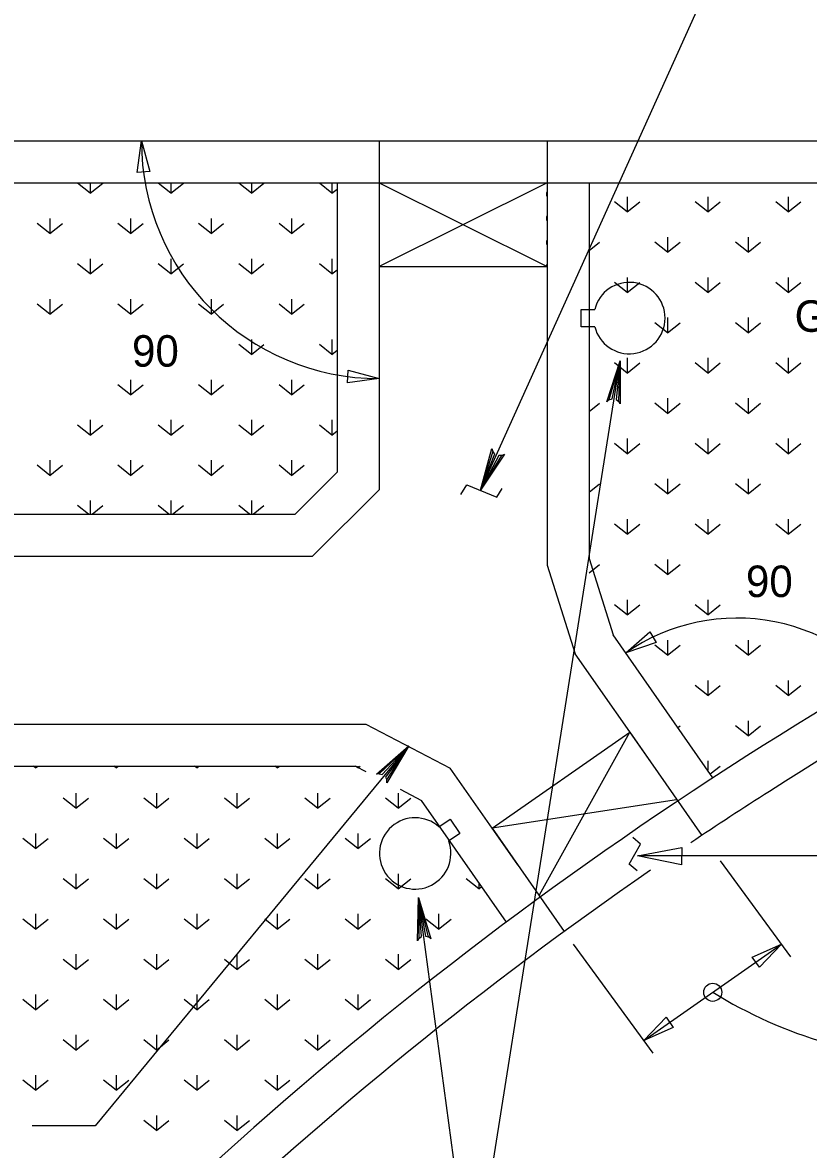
# Model space of a CAD drawing. Extents: x 36 to 940, y -1166 to 1210.
# Drawn here: x 481.8 to 556.7, y -1059.4 to -952.1 of the extents above; entities that cross this region are included whole.
import ezdxf

# ---------------------------------------------------------------- set-up
doc = ezdxf.new("R2010")
doc.units = 0
for name, color, linetype in [('1', 7, 'Continuous'), ('2', 7, 'Continuous'), ('Default', 7, 'Continuous')]:
    doc.layers.add(name, color=color, linetype=linetype)

msp = doc.modelspace()

# ---------------------------------------------------------------- linework, layer by layer
at = {"layer": '1'}
for points in [[(523.61, -997.02), (524.19, -996.11), (527.03, -997.29), (527.56, -996.47)], [(540.43, -1032.88), (539.66, -1032.25), (540.74, -1030.36), (540, -1029.72)]]:
    msp.add_lwpolyline(points, dxfattribs=at)
msp.add_circle((547.62, -1044.46), 0.864, dxfattribs=at)
at = {"layer": '2'}
for p, q in [((515.76, -967.31), (531.84, -975.32)), ((531.72, -967.41), (515.84, -975.32)), ((535.07, -981.05), (535.07, -979.4)), ((535.07, -979.4), (536.37, -979.4)), ((536.37, -981.05), (535.07, -981.05)), ((524.67, -1073.35), (538.81, -984.29)), ((531.11, -1035.18), (539.71, -1019.67)), ((544.15, -1026.13), (526.59, -1028.83)), ((521.52, -1028.69), (522.6, -1027.96)), ((522.6, -1027.96), (523.53, -1029.33)), ((523.53, -1029.33), (522.45, -1030.06)), ((524.67, -1073.35), (519.57, -1035.44))]:
    msp.add_line(p, q, dxfattribs=at)
for points in [[(537.72, -988.02), (538.02, -987.93), (538.81, -984.29), (537.72, -988.02), (537.53, -988.19), (538.81, -984.29), (538.41, -987.98), (538.66, -988.16), (538.81, -984.29), (538.81, -988.4), (538.66, -988.16)], [(527.53, -993.31), (527.22, -993.32), (525.5, -996.63), (527.53, -993.31), (527.77, -993.2), (525.5, -996.63), (526.86, -993.17), (526.66, -992.93), (525.5, -996.63), (526.58, -992.66), (526.66, -992.93)], [(515.83, -1023.64), (516.13, -1023.7), (518.66, -1020.97), (515.83, -1023.64), (515.57, -1023.68), (518.66, -1020.97), (516.43, -1023.95), (516.56, -1024.23), (518.66, -1020.97), (516.57, -1024.51), (516.56, -1024.23)], [(519.61, -1039.33), (519.87, -1039.15), (519.57, -1035.44), (519.61, -1039.33), (519.47, -1039.55), (519.57, -1035.44), (520.25, -1039.1), (520.54, -1039.19), (519.57, -1035.44), (520.75, -1039.38), (520.54, -1039.19)]]:
    msp.add_lwpolyline(points, dxfattribs=at)
for centre, start, end in [((539.67, -980.22), 194.1014, 165.8986), ((519.26, -1031.23), 48.2263, 20.0236)]:
    msp.add_arc(centre, 3.4, start, end, dxfattribs=at)
at = {"layer": 'Default'}
for p, q in [((525.5, -996.63), (548.63, -945.31)), ((452.2, -963.32), (656.79, -963.32)), ((515.84, -963.32), (515.84, -996.57)), ((531.84, -963.32), (531.84, -975.32)), ((452.2, -967.32), (656.79, -967.32)), ((488.29, -968.33), (487.09, -967.37)), ((488.29, -967.32), (488.29, -968.33)), ((488.29, -968.33), (489.49, -967.37)), ((495.97, -968.33), (494.77, -967.37)), ((495.97, -967.32), (495.97, -968.33)), ((495.97, -968.33), (497.17, -967.37)), ((503.65, -968.33), (502.45, -967.37)), ((503.65, -967.32), (503.65, -968.33)), ((503.65, -968.33), (504.85, -967.37)), ((511.33, -968.33), (510.13, -967.37)), ((511.33, -967.32), (511.33, -968.33)), ((511.84, -967.32), (511.84, -994.91)), ((515.84, -967.32), (515.84, -975.32)), ((535.84, -967.32), (535.84, -1003.13)), ((511.33, -968.33), (511.84, -967.93)), ((539.46, -970.1), (538.26, -969.14)), ((539.46, -968.66), (539.46, -970.1)), ((539.46, -970.1), (540.66, -969.14)), ((547.14, -970.1), (545.94, -969.14)), ((547.14, -968.66), (547.14, -970.1)), ((547.14, -970.1), (548.34, -969.14)), ((554.82, -970.1), (553.62, -969.14)), ((554.82, -968.66), (554.82, -970.1)), ((554.82, -970.1), (556.02, -969.14)), ((484.45, -972.17), (483.25, -971.21)), ((484.45, -970.73), (484.45, -972.17)), ((484.45, -972.17), (485.65, -971.21)), ((492.13, -972.17), (490.93, -971.21)), ((492.13, -970.73), (492.13, -972.17)), ((492.13, -972.17), (493.33, -971.21)), ((499.81, -972.17), (498.61, -971.21)), ((499.81, -970.73), (499.81, -972.17)), ((499.81, -972.17), (501.01, -971.21)), ((507.49, -972.17), (506.29, -971.21)), ((507.49, -970.73), (507.49, -972.17)), ((507.49, -972.17), (508.69, -971.21)), ((531.84, -971.32), (531.84, -1003.75)), ((543.3, -972.5), (543.3, -973.94)), ((550.98, -972.5), (550.98, -973.94)), ((535.84, -973.77), (536.82, -972.98)), ((543.3, -973.94), (542.1, -972.98)), ((543.3, -973.94), (544.5, -972.98)), ((550.98, -973.94), (549.78, -972.98)), ((550.98, -973.94), (552.18, -972.98)), ((488.29, -974.57), (488.29, -976.01)), ((495.97, -974.57), (495.97, -976.01)), ((503.65, -974.57), (503.65, -976.01)), ((511.33, -974.57), (511.33, -976.01)), ((488.29, -976.01), (487.09, -975.05)), ((488.29, -976.01), (489.49, -975.05)), ((495.97, -976.01), (494.77, -975.05)), ((495.97, -976.01), (497.17, -975.05)), ((503.65, -976.01), (502.45, -975.05)), ((503.65, -976.01), (504.85, -975.05)), ((511.33, -976.01), (510.13, -975.05)), ((511.33, -976.01), (511.84, -975.61)), ((515.84, -975.32), (531.84, -975.32)), ((539.46, -977.78), (538.26, -976.82)), ((539.46, -976.34), (539.46, -977.78)), ((539.46, -977.78), (540.66, -976.82)), ((547.14, -977.78), (545.94, -976.82)), ((547.14, -976.34), (547.14, -977.78)), ((547.14, -977.78), (548.34, -976.82)), ((554.82, -977.78), (553.62, -976.82)), ((554.82, -976.34), (554.82, -977.78)), ((554.82, -977.78), (556.02, -976.82)), ((484.45, -979.85), (483.25, -978.89)), ((484.45, -978.41), (484.45, -979.85)), ((484.45, -979.85), (485.65, -978.89)), ((492.13, -979.85), (490.93, -978.89)), ((492.13, -978.41), (492.13, -979.85)), ((492.13, -979.85), (493.33, -978.89)), ((499.81, -979.85), (498.61, -978.89)), ((499.81, -978.41), (499.81, -979.85)), ((499.81, -979.85), (501.01, -978.89)), ((507.49, -979.85), (506.29, -978.89)), ((507.49, -978.41), (507.49, -979.85)), ((507.49, -979.85), (508.69, -978.89)), ((543.3, -980.18), (543.3, -981.62)), ((550.98, -980.18), (550.98, -981.62)), ((543.3, -981.62), (542.1, -980.66)), ((543.3, -981.62), (544.5, -980.66)), ((550.98, -981.62), (549.78, -980.66)), ((550.98, -981.62), (552.18, -980.66)), ((503.65, -982.25), (503.65, -983.69)), ((511.33, -982.25), (511.33, -983.69)), ((503.65, -983.69), (502.45, -982.73)), ((503.65, -983.69), (504.85, -982.73)), ((511.33, -983.69), (510.13, -982.73)), ((511.33, -983.69), (511.84, -983.29)), ((539.46, -985.46), (538.26, -984.5)), ((539.46, -984.02), (539.46, -985.46)), ((539.46, -985.46), (540.66, -984.5)), ((547.14, -985.46), (545.94, -984.5)), ((547.14, -984.02), (547.14, -985.46)), ((547.14, -985.46), (548.34, -984.5)), ((554.82, -985.46), (553.62, -984.5)), ((554.82, -984.02), (554.82, -985.46)), ((554.82, -985.46), (556.02, -984.5)), ((492.13, -987.53), (490.93, -986.57)), ((492.13, -986.09), (492.13, -987.53)), ((492.13, -987.53), (493.33, -986.57)), ((499.81, -987.53), (498.61, -986.57)), ((499.81, -986.09), (499.81, -987.53)), ((499.81, -987.53), (501.01, -986.57)), ((507.49, -987.53), (506.29, -986.57)), ((507.49, -986.09), (507.49, -987.53)), ((507.49, -987.53), (508.69, -986.57)), ((535.84, -989.13), (536.82, -988.34)), ((543.3, -989.3), (542.1, -988.34)), ((543.3, -987.86), (543.3, -989.3)), ((543.3, -989.3), (544.5, -988.34)), ((550.98, -989.3), (549.78, -988.34)), ((550.98, -987.86), (550.98, -989.3)), ((550.98, -989.3), (552.18, -988.34)), ((488.29, -989.93), (488.29, -991.37)), ((495.97, -989.93), (495.97, -991.37)), ((503.65, -989.93), (503.65, -991.37)), ((511.33, -989.93), (511.33, -991.37)), ((488.29, -991.37), (487.09, -990.41)), ((488.29, -991.37), (489.49, -990.41)), ((495.97, -991.37), (494.77, -990.41)), ((495.97, -991.37), (497.17, -990.41)), ((503.65, -991.37), (502.45, -990.41)), ((503.65, -991.37), (504.85, -990.41)), ((511.33, -991.37), (510.13, -990.41)), ((511.33, -991.37), (511.84, -990.97)), ((539.46, -991.7), (539.46, -993.14)), ((547.14, -991.7), (547.14, -993.14)), ((554.82, -991.7), (554.82, -993.14)), ((539.46, -993.14), (538.26, -992.18)), ((539.46, -993.14), (540.66, -992.18)), ((547.14, -993.14), (545.94, -992.18)), ((547.14, -993.14), (548.34, -992.18)), ((554.82, -993.14), (553.62, -992.18)), ((554.82, -993.14), (556.02, -992.18)), ((484.45, -995.21), (483.25, -994.25)), ((484.45, -993.77), (484.45, -995.21)), ((484.45, -995.21), (485.65, -994.25)), ((492.13, -995.21), (490.93, -994.25)), ((492.13, -993.77), (492.13, -995.21)), ((492.13, -995.21), (493.33, -994.25)), ((499.81, -995.21), (498.61, -994.25)), ((499.81, -993.77), (499.81, -995.21)), ((499.81, -995.21), (501.01, -994.25)), ((507.49, -995.21), (506.29, -994.25)), ((507.49, -993.77), (507.49, -995.21)), ((507.49, -995.21), (508.69, -994.25)), ((507.84, -998.91), (511.84, -994.91)), ((535.84, -996.81), (536.82, -996.02)), ((543.3, -996.98), (542.1, -996.02)), ((543.3, -995.54), (543.3, -996.98)), ((543.3, -996.98), (544.5, -996.02)), ((550.98, -996.98), (549.78, -996.02)), ((550.98, -995.54), (550.98, -996.98)), ((550.98, -996.98), (552.18, -996.02)), ((509.49, -1002.91), (515.84, -996.57)), ((488.12, -998.91), (487.09, -998.09)), ((488.29, -997.61), (488.29, -998.91)), ((488.47, -998.91), (489.49, -998.09)), ((495.8, -998.91), (494.77, -998.09)), ((495.97, -997.61), (495.97, -998.91)), ((496.15, -998.91), (497.17, -998.09)), ((503.48, -998.91), (502.45, -998.09)), ((503.65, -997.61), (503.65, -998.91)), ((503.83, -998.91), (504.85, -998.09)), ((448.2, -998.91), (507.84, -998.91)), ((539.46, -999.38), (539.46, -1000.82)), ((547.14, -999.38), (547.14, -1000.82)), ((554.82, -999.38), (554.82, -1000.82)), ((539.46, -1000.82), (538.26, -999.86)), ((539.46, -1000.82), (540.66, -999.86)), ((547.14, -1000.82), (545.94, -999.86)), ((547.14, -1000.82), (548.34, -999.86)), ((554.82, -1000.82), (553.62, -999.86)), ((554.82, -1000.82), (556.02, -999.86)), ((444.2, -1002.91), (509.49, -1002.91)), ((531.84, -1003.75), (534.5, -1012.2)), ((535.84, -1003.13), (538.13, -1010.41)), ((535.84, -1004.49), (536.82, -1003.7)), ((543.3, -1004.66), (542.1, -1003.7)), ((543.3, -1003.22), (543.3, -1004.66)), ((543.3, -1004.66), (544.5, -1003.7)), ((539.46, -1007.06), (539.46, -1008.5)), ((547.14, -1007.06), (547.14, -1008.5)), ((539.46, -1008.5), (538.26, -1007.54)), ((539.46, -1008.5), (540.66, -1007.54)), ((547.14, -1008.5), (545.94, -1007.54)), ((547.14, -1008.5), (548.34, -1007.54)), ((547.63, -1024.02), (538.13, -1010.41)), ((543.3, -1012.34), (542.1, -1011.38)), ((543.3, -1010.9), (543.3, -1012.34)), ((543.3, -1012.34), (544.5, -1011.38)), ((550.98, -1012.34), (549.78, -1011.38)), ((550.98, -1010.9), (550.98, -1012.34)), ((550.98, -1012.34), (552.18, -1011.38)), ((542.15, -1023.15), (534.5, -1012.2)), ((547.14, -1016.18), (545.94, -1015.22)), ((547.14, -1014.74), (547.14, -1016.18)), ((547.14, -1016.18), (548.34, -1015.22)), ((554.82, -1016.18), (553.62, -1015.22)), ((554.82, -1014.74), (554.82, -1016.18)), ((554.82, -1016.18), (556.02, -1015.22)), ((444.2, -1018.91), (514.56, -1018.91)), ((514.56, -1018.91), (522.59, -1023.1)), ((550.98, -1018.58), (550.98, -1020.02)), ((526.59, -1028.83), (539.71, -1019.67)), ((539.71, -1019.67), (546.59, -1029.51)), ((544.29, -1019.23), (544.5, -1019.06)), ((550.98, -1020.02), (549.78, -1019.06)), ((550.98, -1020.02), (552.18, -1019.06)), ((518.66, -1020.97), (488.77, -1057.19)), ((448.2, -1022.91), (513.58, -1022.91)), ((483.08, -1023.08), (482.87, -1022.91)), ((483.08, -1022.91), (483.08, -1023.08)), ((483.08, -1023.08), (483.29, -1022.91)), ((490.76, -1023.08), (490.55, -1022.91)), ((490.76, -1022.91), (490.76, -1023.08)), ((490.76, -1023.08), (490.97, -1022.91)), ((498.44, -1023.08), (498.23, -1022.91)), ((498.44, -1022.91), (498.44, -1023.08)), ((498.44, -1023.08), (498.65, -1022.91)), ((506.12, -1023.08), (505.91, -1022.91)), ((506.12, -1022.91), (506.12, -1023.08)), ((506.12, -1023.08), (506.33, -1022.91)), ((513.58, -1022.91), (514.56, -1023.42)), ((513.8, -1023.08), (513.59, -1022.91)), ((513.8, -1022.91), (513.8, -1023.08)), ((513.8, -1023.08), (514.01, -1022.91)), ((529.03, -1032.32), (522.59, -1023.1)), ((547.14, -1022.42), (547.14, -1023.31)), ((547.38, -1023.66), (548.34, -1022.9)), ((517.83, -1025.12), (519.87, -1026.19)), ((486.92, -1026.92), (485.72, -1025.96)), ((486.92, -1025.48), (486.92, -1026.92)), ((486.92, -1026.92), (488.12, -1025.96)), ((494.6, -1026.92), (493.4, -1025.96)), ((494.6, -1025.48), (494.6, -1026.92)), ((494.6, -1026.92), (495.8, -1025.96)), ((502.28, -1026.92), (501.08, -1025.96)), ((502.28, -1025.48), (502.28, -1026.92)), ((502.28, -1026.92), (503.48, -1025.96)), ((509.96, -1026.92), (508.76, -1025.96)), ((509.96, -1025.48), (509.96, -1026.92)), ((509.96, -1026.92), (511.16, -1025.96)), ((517.64, -1026.92), (516.44, -1025.96)), ((517.64, -1025.48), (517.64, -1026.92)), ((517.64, -1026.92), (518.84, -1025.96)), ((527.96, -1037.77), (519.87, -1026.19)), ((483.08, -1029.32), (483.08, -1030.76)), ((490.76, -1029.32), (490.76, -1030.76)), ((498.44, -1029.32), (498.44, -1030.76)), ((506.12, -1029.32), (506.12, -1030.76)), ((513.8, -1029.32), (513.8, -1030.76)), ((526.59, -1028.83), (533.46, -1038.67)), ((483.08, -1030.76), (481.88, -1029.8)), ((483.08, -1030.76), (484.28, -1029.8)), ((490.76, -1030.76), (489.56, -1029.8)), ((490.76, -1030.76), (491.96, -1029.8)), ((498.44, -1030.76), (497.24, -1029.8)), ((498.44, -1030.76), (499.64, -1029.8)), ((506.12, -1030.76), (504.92, -1029.8)), ((506.12, -1030.76), (507.32, -1029.8)), ((513.8, -1030.76), (512.6, -1029.8)), ((513.8, -1030.76), (515, -1029.8)), ((557.97, -1031.45), (540.45, -1031.45)), ((555.06, -1041.08), (548.36, -1031.93)), ((486.92, -1034.6), (485.72, -1033.64)), ((486.92, -1033.16), (486.92, -1034.6)), ((486.92, -1034.6), (488.12, -1033.64)), ((494.6, -1034.6), (493.4, -1033.64)), ((494.6, -1033.16), (494.6, -1034.6)), ((494.6, -1034.6), (495.8, -1033.64)), ((502.28, -1034.6), (501.08, -1033.64)), ((502.28, -1033.16), (502.28, -1034.6)), ((502.28, -1034.6), (503.48, -1033.64)), ((509.96, -1034.6), (508.76, -1033.64)), ((509.96, -1033.16), (509.96, -1034.6)), ((509.96, -1034.6), (511.16, -1033.64)), ((517.64, -1034.6), (516.44, -1033.64)), ((517.64, -1033.16), (517.64, -1034.6)), ((517.64, -1034.6), (518.84, -1033.64)), ((525.32, -1034.6), (524.12, -1033.64)), ((525.32, -1033.99), (525.32, -1034.6)), ((525.32, -1034.6), (525.59, -1034.38)), ((483.08, -1037), (483.08, -1038.44)), ((490.76, -1037), (490.76, -1038.44)), ((498.44, -1037), (498.44, -1038.44)), ((506.12, -1037), (506.12, -1038.44)), ((513.8, -1037), (513.8, -1038.44)), ((521.48, -1037), (521.48, -1038.44)), ((483.08, -1038.44), (481.88, -1037.48)), ((483.08, -1038.44), (484.28, -1037.48)), ((490.76, -1038.44), (489.56, -1037.48)), ((490.76, -1038.44), (491.96, -1037.48)), ((498.44, -1038.44), (497.24, -1037.48)), ((498.44, -1038.44), (499.64, -1037.48)), ((506.12, -1038.44), (504.92, -1037.48)), ((506.12, -1038.44), (507.32, -1037.48)), ((513.8, -1038.44), (512.6, -1037.48)), ((513.8, -1038.44), (515, -1037.48)), ((521.48, -1038.44), (520.28, -1037.48)), ((521.48, -1038.44), (522.68, -1037.48)), ((541.94, -1050.25), (534.35, -1039.88)), ((541.06, -1049.04), (554.18, -1039.87)), ((486.92, -1042.28), (485.72, -1041.32)), ((486.92, -1040.84), (486.92, -1042.28)), ((486.92, -1042.28), (488.12, -1041.32)), ((494.6, -1042.28), (493.4, -1041.32)), ((494.6, -1040.84), (494.6, -1042.28)), ((494.6, -1042.28), (495.8, -1041.32)), ((502.28, -1042.28), (501.08, -1041.32)), ((502.28, -1040.84), (502.28, -1042.28)), ((502.28, -1042.28), (503.48, -1041.32)), ((509.96, -1042.28), (508.76, -1041.32)), ((509.96, -1040.84), (509.96, -1042.28)), ((509.96, -1042.28), (511.16, -1041.32)), ((517.64, -1042.28), (516.44, -1041.32)), ((517.64, -1040.84), (517.64, -1042.28)), ((517.64, -1042.28), (518.84, -1041.32)), ((483.08, -1044.68), (483.08, -1046.12)), ((490.76, -1044.68), (490.76, -1046.12)), ((498.44, -1044.68), (498.44, -1046.12)), ((506.12, -1044.68), (506.12, -1046.12)), ((513.8, -1044.68), (513.8, -1046.12)), ((483.08, -1046.12), (481.88, -1045.16)), ((483.08, -1046.12), (484.28, -1045.16)), ((490.76, -1046.12), (489.56, -1045.16)), ((490.76, -1046.12), (491.96, -1045.16)), ((498.44, -1046.12), (497.24, -1045.16)), ((498.44, -1046.12), (499.64, -1045.16)), ((506.12, -1046.12), (504.92, -1045.16)), ((506.12, -1046.12), (507.32, -1045.16)), ((513.8, -1046.12), (512.6, -1045.16)), ((513.8, -1046.12), (515, -1045.16)), ((486.92, -1049.96), (485.72, -1049)), ((486.92, -1048.52), (486.92, -1049.96)), ((486.92, -1049.96), (488.12, -1049)), ((494.6, -1049.96), (493.4, -1049)), ((494.6, -1048.52), (494.6, -1049.96)), ((494.6, -1049.96), (495.8, -1049)), ((502.28, -1049.96), (501.08, -1049)), ((502.28, -1048.52), (502.28, -1049.96)), ((502.28, -1049.96), (503.48, -1049)), ((509.96, -1049.96), (508.76, -1049)), ((509.96, -1048.52), (509.96, -1049.96)), ((509.96, -1049.96), (511.16, -1049)), ((483.08, -1053.8), (481.88, -1052.84)), ((483.08, -1052.36), (483.08, -1053.8)), ((483.08, -1053.8), (484.28, -1052.84)), ((490.76, -1053.8), (489.56, -1052.84)), ((490.76, -1052.36), (490.76, -1053.8)), ((490.76, -1053.8), (491.96, -1052.84)), ((498.44, -1053.8), (497.24, -1052.84)), ((498.44, -1052.36), (498.44, -1053.8)), ((498.44, -1053.8), (499.64, -1052.84)), ((506.12, -1053.8), (504.92, -1052.84)), ((506.12, -1052.36), (506.12, -1053.8)), ((506.12, -1053.8), (507.32, -1052.84)), ((494.6, -1056.2), (494.6, -1057.64)), ((502.28, -1056.2), (502.28, -1057.64)), ((488.77, -1057.19), (482.77, -1057.19)), ((494.6, -1057.64), (493.4, -1056.68)), ((494.6, -1057.64), (495.8, -1056.68)), ((502.28, -1057.64), (501.08, -1056.68)), ((502.28, -1057.64), (503.48, -1056.68))]:
    msp.add_line(p, q, dxfattribs=at)
for points in [[(492.77, -966.35), (493.17, -963.32), (493.97, -966.27)], [(512.88, -985.19), (515.84, -985.98), (512.8, -986.38)], [(542.22, -1011.13), (539.32, -1012.13), (541.61, -1010.1)], [(544.64, -1032.33), (540.45, -1031.45), (544.66, -1030.65)], [(551.37, -1041.1), (554.18, -1039.87), (552.06, -1042.08)], [(543.86, -1047.81), (541.06, -1049.04), (543.17, -1046.83)]]:
    msp.add_lwpolyline(points, close=True, dxfattribs=at)
for centre, radius, start, end in [((515.84, -963.32), 22.67, 180, 270), ((532.29, -968.41), 0.517, 151.496, 208.504), ((532.29, -970.71), 0.517, 151.496, 180), ((532.29, -970.72), 0.517, 180, 208.504), ((532.29, -973.02), 0.517, 151.496, 208.504), ((532.29, -975.32), 0.517, 151.496, 180), ((753.46, -1339.64), 376.8, 104.7063, 122.5261), ((753.46, -1339.64), 372.8, 104.7063, 122.5261), ((549.92, -1027.29), 18.49, 32.5261, 124.9342), ((753.46, -1339.64), 376.8, 122.5261, 142.2884), ((753.46, -1339.64), 372.8, 122.5261, 123.9004), ((753.46, -1339.64), 372.8, 124.6158, 142.2884), ((571.07, -1006.38), 44.72, 238.3693, 268.7424)]:
    msp.add_arc(centre, radius, start, end, dxfattribs=at)

# ---------------------------------------------------------------- texts
for s, p in [('GRASS ISLAND', (555.42, -981.53)), ('90', (492.28, -984.85)), ('90', (550.78, -1006.8))]:
    msp.add_text(s, height=3, dxfattribs=at).set_placement(p)

doc.saveas('drawing.dxf')
